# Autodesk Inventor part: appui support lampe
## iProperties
Created: 2011-01
Part Number: appui support lampe
Document SubType Name: Modeling
Designer: eric
Density: 1 g/cm^3
Mass: 3.94918 g
Surface Area: 86.668 cm^2
Volume: 3.94918 cm^3
Author: eric
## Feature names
1. Base1
